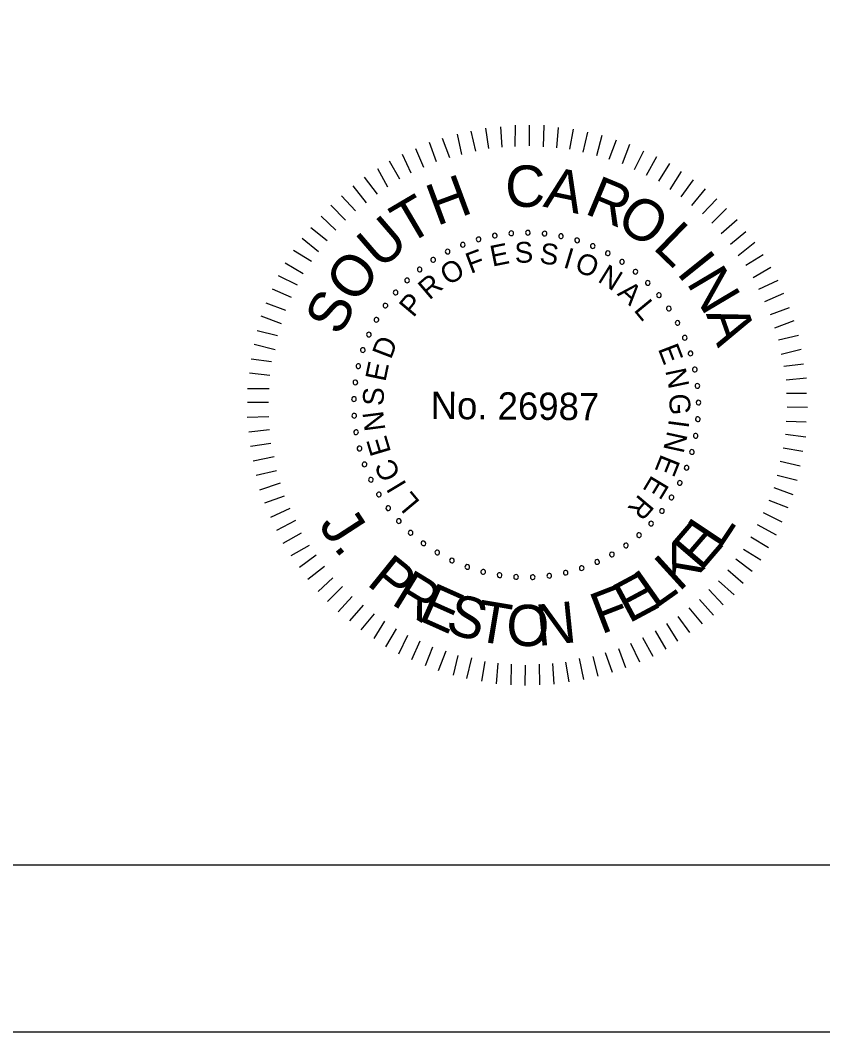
# Model space of a CAD drawing. Extents: x -125.5 to -89.4, y -5.1 to 16.9.
# Drawn here: x -102.74 to -100.338, y -5.066 to -2.039 of the extents above; entities that cross this region are included whole.
import ezdxf

# ---------------------------------------------------------------- set-up
doc = ezdxf.new("R2010")
doc.units = 0
for name, color, linetype in [('BR_BORDER LINES', 7, 'Continuous'), ('BR_TEXT', 7, 'Continuous'), ('Level 31', 7, 'Continuous')]:
    doc.layers.add(name, color=color, linetype=linetype)

msp = doc.modelspace()

# ---------------------------------------------------------------- linework, layer by layer
at = {"layer": 'BR_BORDER LINES'}
msp.add_line((-123.6994, -4.5662), (-90.0334, -4.5662), dxfattribs=at)
at = {"layer": 'BR_TEXT'}
for p, q in [((-101.2977, -2.419), (-101.3015, -2.3581)), ((-101.2582, -2.4168), (-101.2576, -2.3524)), ((-101.2161, -2.4146), (-101.2156, -2.3528)), ((-101.1741, -2.4175), (-101.1718, -2.3531)), ((-101.1338, -2.4204), (-101.129, -2.3595)), ((-101.418, -2.4404), (-101.4312, -2.3793)), ((-101.3767, -2.4304), (-101.3908, -2.3711)), ((-101.3372, -2.423), (-101.3461, -2.362)), ((-101.0952, -2.425), (-101.0844, -2.3642)), ((-101.0549, -2.4331), (-101.0407, -2.374)), ((-101.0138, -2.4437), (-100.9979, -2.3829)), ((-101.4937, -2.4629), (-101.5147, -2.4044)), ((-101.4541, -2.4504), (-101.476, -2.3927)), ((-100.977, -2.4543), (-100.9551, -2.397)), ((-100.9376, -2.4675), (-100.9157, -2.4093)), ((-101.5695, -2.4966), (-101.5957, -2.4406)), ((-101.5325, -2.4798), (-101.556, -2.4238)), ((-100.9017, -2.485), (-100.8738, -2.4294)), ((-100.8658, -2.5024), (-100.8345, -2.4469)), ((-101.604, -2.5144), (-101.6344, -2.46)), ((-100.8282, -2.5208), (-100.796, -2.467)), ((-101.6704, -2.5593), (-101.7095, -2.5083)), ((-101.6394, -2.5381), (-101.6698, -2.4838)), ((-100.795, -2.5451), (-100.761, -2.4913)), ((-101.7041, -2.5847), (-101.744, -2.5346)), ((-100.7617, -2.5668), (-100.7252, -2.5165)), ((-101.7369, -2.6094), (-101.7786, -2.5644)), ((-100.7293, -2.5928), (-100.6886, -2.5434)), ((-101.7663, -2.6366), (-101.8106, -2.5925)), ((-100.6977, -2.618), (-100.6545, -2.5737)), ((-100.6697, -2.6456), (-100.6264, -2.6022)), ((-101.7958, -2.6673), (-101.8392, -2.6248)), ((-101.8209, -2.6988), (-101.8704, -2.6598)), ((-100.6416, -2.6768), (-100.594, -2.6351)), ((-101.8469, -2.732), (-101.8964, -2.6922)), ((-100.6144, -2.7088), (-100.5677, -2.6705)), ((-100.5906, -2.7424), (-100.5414, -2.7033)), ((-101.8686, -2.761), (-101.9224, -2.728)), ((-100.5686, -2.7718), (-100.516, -2.7396)), ((-101.893, -2.7977), (-101.9467, -2.7656)), ((-100.5466, -2.8089), (-100.4931, -2.7776)), ((-101.9104, -2.8319), (-101.9668, -2.804)), ((-101.9279, -2.8687), (-101.9852, -2.8433)), ((-100.5288, -2.8433), (-100.4711, -2.8164)), ((-100.5111, -2.8804), (-100.4543, -2.856)), ((-101.9454, -2.9072), (-102.0035, -2.8852)), ((-100.4943, -2.9192), (-100.4374, -2.8982)), ((-101.9577, -2.9474), (-102.0193, -2.9246)), ((-100.4809, -2.9596), (-100.4232, -2.9378)), ((-101.97, -2.9833), (-102.0308, -2.9682)), ((-100.4708, -2.9957), (-100.4107, -2.9816)), ((-101.9772, -3.0253), (-102.0397, -3.0094)), ((-100.4626, -3.0378), (-100.4024, -3.0229)), ((-101.9878, -3.0613), (-102.0487, -3.0531)), ((-100.4543, -3.074), (-100.3951, -3.0667)), ((-101.9925, -3.1024), (-102.0542, -3.0951)), ((-100.4478, -3.1152), (-100.3868, -3.1088)), ((-101.9954, -3.1419), (-102.0597, -3.1414)), ((-100.4464, -3.1547), (-100.3863, -3.1552)), ((-101.9974, -3.183), (-102.06, -3.1825)), ((-100.4442, -3.1959), (-100.3833, -3.1964)), ((-101.9961, -3.226), (-102.0604, -3.2272)), ((-100.4471, -3.2388), (-100.3871, -3.241)), ((-101.9938, -3.2646), (-102.0556, -3.2718)), ((-100.4492, -3.2774), (-100.3883, -3.2856)), ((-101.9898, -3.3058), (-102.0509, -3.3148)), ((-100.4564, -3.3185), (-100.3972, -3.3284)), ((-101.9799, -3.3454), (-102.0426, -3.3586)), ((-100.4653, -3.3579), (-100.4053, -3.3721)), ((-101.9733, -3.3875), (-102.0344, -3.4016)), ((-100.4742, -3.3999), (-100.4143, -3.415)), ((-101.9616, -3.4245), (-102.0236, -3.4454)), ((-100.4848, -3.4367), (-100.4275, -3.4586)), ((-101.95, -3.4632), (-102.0085, -3.4842)), ((-100.4989, -3.4752), (-100.4424, -3.4971)), ((-101.9331, -3.5003), (-101.9908, -3.5272)), ((-101.9162, -3.5364), (-101.9731, -3.566)), ((-100.5163, -3.512), (-100.4599, -3.5399)), ((-100.5346, -3.5479), (-100.4774, -3.5784)), ((-101.8994, -3.5735), (-101.9537, -3.6048)), ((-100.553, -3.5846), (-100.5, -3.6168)), ((-101.8756, -3.6106), (-101.93, -3.6419)), ((-100.5756, -3.6213), (-100.5235, -3.6535)), ((-101.8544, -3.6399), (-101.9045, -3.6764)), ((-100.5981, -3.6503), (-100.5495, -3.6876)), ((-101.829, -3.6736), (-101.8791, -3.7127)), ((-100.6224, -3.6836), (-100.5764, -3.7234)), ((-101.8043, -3.7073), (-101.8485, -3.7481)), ((-100.6502, -3.7168), (-100.6033, -3.7584)), ((-101.7754, -3.7333), (-101.8204, -3.7784)), ((-100.6787, -3.7423), (-100.6362, -3.7882)), ((-101.7465, -3.7636), (-101.7889, -3.8095)), ((-100.7073, -3.7721), (-100.6648, -3.8188)), ((-101.714, -3.7895), (-101.7548, -3.8364)), ((-100.7392, -3.7976), (-100.6993, -3.8452)), ((-101.6808, -3.8156), (-101.7207, -3.8633)), ((-101.6501, -3.8373), (-101.6814, -3.8894)), ((-100.8057, -3.8443), (-100.7727, -3.8969)), ((-100.772, -3.8231), (-100.7364, -3.8714)), ((-101.6151, -3.8599), (-101.6464, -3.9137)), ((-100.8393, -3.8663), (-100.808, -3.9206)), ((-101.5809, -3.8799), (-101.608, -3.9355)), ((-101.5442, -3.8974), (-101.5687, -3.953)), ((-100.9135, -3.9026), (-100.8865, -3.9586)), ((-100.8773, -3.8857), (-100.8468, -3.9418)), ((-101.5057, -3.9149), (-101.5276, -3.9713)), ((-101.4663, -3.9272), (-101.4891, -3.9854)), ((-100.9892, -3.9311), (-100.9682, -3.9897)), ((-100.9496, -3.9194), (-100.9286, -3.9763)), ((-101.4304, -3.9395), (-101.4446, -3.9986)), ((-101.3892, -3.9467), (-101.4044, -4.0084)), ((-101.3499, -3.9582), (-101.3598, -4.0165)), ((-101.3104, -3.9628), (-101.3152, -4.0246)), ((-101.271, -3.9657), (-101.2715, -4.0275)), ((-101.1466, -3.9642), (-101.1428, -4.026)), ((-101.1079, -3.9602), (-101.098, -4.0186)), ((-101.0675, -3.9494), (-101.0542, -4.0113)), ((-101.0262, -3.9429), (-101.0112, -4.0022)), ((-101.229, -3.9686), (-101.2295, -4.0296)), ((-101.1869, -3.9664), (-101.1857, -4.0282))]:
    msp.add_line(p, q, dxfattribs=at)
for centre, start, end in [((-101.3681, -2.6945), 16.1422, 196.1422), ((-101.3681, -2.6945), 196.1422, 16.1422), ((-101.3196, -2.6831), 10.6038, 190.6038), ((-101.3196, -2.6831), 190.6038, 10.6038), ((-101.2702, -2.6764), 5.0653, 185.0653), ((-101.2702, -2.6764), 185.0653, 5.0653), ((-101.2204, -2.6745), 359.5268, 179.5268), ((-101.2204, -2.6745), 179.5268, 359.5268), ((-101.1707, -2.6774), 173.9884, 353.9884), ((-101.1707, -2.6774), 353.9884, 173.9884), ((-101.1214, -2.6851), 168.4499, 348.4499), ((-101.1214, -2.6851), 348.4499, 168.4499), ((-101.0732, -2.6976), 342.9114, 162.9114), ((-101.4607, -2.7311), 27.2191, 207.2191), ((-101.4153, -2.7106), 21.6807, 201.6807), ((-101.4153, -2.7106), 201.6807, 21.6807), ((-101.0732, -2.6976), 162.9114, 342.9114), ((-101.0263, -2.7146), 157.373, 337.373), ((-101.0263, -2.7146), 337.373, 157.373), ((-101.5039, -2.7559), 32.7576, 212.7576), ((-101.5039, -2.7559), 212.7576, 32.7576), ((-101.4607, -2.7311), 207.2191, 27.2191), ((-100.9814, -2.736), 151.8345, 331.8345), ((-100.9814, -2.736), 331.8345, 151.8345), ((-100.9387, -2.7617), 326.2961, 146.2961), ((-101.5445, -2.7848), 38.2961, 218.2961), ((-101.5445, -2.7848), 218.2961, 38.2961), ((-100.9387, -2.7617), 146.2961, 326.2961), ((-100.8987, -2.7914), 320.7576, 140.7576), ((-101.5821, -2.8175), 43.8345, 223.8345), ((-101.5821, -2.8175), 223.8345, 43.8345), ((-100.8987, -2.7914), 140.7576, 320.7576), ((-100.8617, -2.8249), 135.2191, 315.2191), ((-100.8617, -2.8249), 315.2191, 135.2191), ((-101.6164, -2.8536), 49.373, 229.373), ((-101.6164, -2.8536), 229.373, 49.373), ((-100.8282, -2.8617), 129.6807, 309.6807), ((-100.8282, -2.8617), 309.6807, 129.6807), ((-101.6471, -2.8929), 54.9114, 234.9114), ((-101.6471, -2.8929), 234.9114, 54.9114), ((-100.7983, -2.9016), 124.1422, 304.1422), ((-100.7983, -2.9016), 304.1422, 124.1422), ((-101.6738, -2.935), 60.4499, 240.4499), ((-101.6738, -2.935), 240.4499, 60.4499), ((-100.7724, -2.9442), 118.6038, 298.6038), ((-100.7724, -2.9442), 298.6038, 118.6038), ((-101.6964, -2.9794), 65.9884, 245.9884), ((-101.6964, -2.9794), 245.9884, 65.9884), ((-100.7508, -2.9891), 113.0653, 293.0653), ((-100.7508, -2.9891), 293.0653, 113.0653), ((-101.7145, -3.0258), 71.5268, 251.5268), ((-101.7145, -3.0258), 251.5268, 71.5268), ((-100.7336, -3.0359), 107.5268, 287.5268), ((-100.7336, -3.0359), 287.5268, 107.5268), ((-101.7281, -3.0738), 77.0653, 257.0653), ((-101.7281, -3.0738), 257.0653, 77.0653), ((-100.721, -3.0841), 101.9884, 281.9884), ((-100.721, -3.0841), 281.9884, 101.9884), ((-101.737, -3.1228), 82.6038, 262.6038), ((-101.737, -3.1228), 262.6038, 82.6038), ((-100.7131, -3.1333), 96.4499, 276.4499), ((-100.7131, -3.1333), 276.4499, 96.4499), ((-101.7411, -3.1724), 88.1422, 268.1422), ((-101.7411, -3.1724), 268.1422, 88.1422), ((-100.71, -3.183), 90.9114, 270.9114), ((-100.71, -3.183), 270.9114, 90.9114), ((-101.7404, -3.2223), 93.6807, 273.6807), ((-101.7404, -3.2223), 273.6807, 93.6807), ((-100.7118, -3.2328), 85.373, 265.373), ((-100.7118, -3.2328), 265.373, 85.373), ((-101.7349, -3.2718), 99.2191, 279.2191), ((-101.7349, -3.2718), 279.2191, 99.2191), ((-100.7183, -3.2822), 79.8345, 259.8345), ((-100.7183, -3.2822), 259.8345, 79.8345), ((-101.7246, -3.3206), 104.7576, 284.7576), ((-101.7246, -3.3206), 284.7576, 104.7576), ((-100.7295, -3.3308), 74.2961, 254.2961), ((-100.7295, -3.3308), 254.2961, 74.2961), ((-101.7097, -3.3681), 110.2961, 290.2961), ((-101.7097, -3.3681), 290.2961, 110.2961), ((-100.7454, -3.378), 68.7576, 248.7576), ((-100.7454, -3.378), 248.7576, 68.7576), ((-101.6903, -3.414), 115.8345, 295.8345), ((-101.6903, -3.414), 295.8345, 115.8345), ((-100.7658, -3.4235), 63.2191, 243.2191), ((-100.7658, -3.4235), 243.2191, 63.2191), ((-101.6665, -3.4578), 301.373, 121.373), ((-101.6665, -3.4578), 121.373, 301.373), ((-100.7904, -3.4668), 57.6807, 237.6807), ((-100.7904, -3.4668), 237.6807, 57.6807), ((-101.6386, -3.4991), 126.9114, 306.9114), ((-101.6386, -3.4991), 306.9114, 126.9114), ((-100.8192, -3.5075), 52.1422, 232.1422), ((-100.8192, -3.5075), 232.1422, 52.1422), ((-101.6069, -3.5375), 132.4499, 312.4499), ((-101.6069, -3.5375), 312.4499, 132.4499), ((-100.8517, -3.5452), 46.6038, 226.6038), ((-100.8517, -3.5452), 226.6038, 46.6038), ((-101.5716, -3.5727), 137.9884, 317.9884), ((-101.5716, -3.5727), 317.9884, 137.9884), ((-101.5331, -3.6043), 143.5268, 323.5268), ((-101.5331, -3.6043), 323.5268, 143.5268), ((-100.8877, -3.5797), 41.0653, 221.0653), ((-100.8877, -3.5797), 221.0653, 41.0653), ((-101.4917, -3.632), 149.0653, 329.0653), ((-101.4917, -3.632), 329.0653, 149.0653), ((-100.9688, -3.6374), 29.9884, 209.9884), ((-100.9269, -3.6105), 35.5268, 215.5268), ((-100.9269, -3.6105), 215.5268, 35.5268), ((-101.4478, -3.6556), 154.6038, 334.6038), ((-101.4478, -3.6556), 334.6038, 154.6038), ((-101.0132, -3.6601), 24.4499, 204.4499), ((-101.0132, -3.6601), 204.4499, 24.4499), ((-100.9688, -3.6374), 209.9884, 29.9884), ((-101.4018, -3.6749), 160.1422, 340.1422), ((-101.4018, -3.6749), 340.1422, 160.1422), ((-101.3542, -3.6896), 165.6807, 345.6807), ((-101.3542, -3.6896), 345.6807, 165.6807), ((-101.3054, -3.6997), 351.2191, 171.2191), ((-101.1074, -3.6921), 13.373, 193.373), ((-101.1074, -3.6921), 193.373, 13.373), ((-101.0595, -3.6784), 18.9114, 198.9114), ((-101.0595, -3.6784), 198.9114, 18.9114), ((-101.3054, -3.6997), 171.2191, 351.2191), ((-101.2559, -3.705), 356.7576, 176.7576), ((-101.2559, -3.705), 176.7576, 356.7576), ((-101.2061, -3.7055), 2.2961, 182.2961), ((-101.2061, -3.7055), 182.2961, 2.2961), ((-101.1564, -3.7012), 7.8345, 187.8345), ((-101.1564, -3.7012), 187.8345, 7.8345)]:
    msp.add_arc(centre, 0.00701, start, end, dxfattribs=at)
at = {"layer": 'Level 31'}
msp.add_lwpolyline([(-125.5328, 16.9339), (-125.5328, -5.0661), (-89.5328, -5.0661), (-89.5328, 16.9339)], dxfattribs=at)

# ---------------------------------------------------------------- texts
at = {"layer": 'BR_TEXT'}
for s, height, rotation, p in [('C', 0.1241, 359.5482, (-101.2889, -2.5969)), ('H', 0.1241, 20.3637, (-101.4933, -2.6552)), ('A', 0.1241, 348.1981, (-101.1775, -2.5961)), ('R', 0.1241, 337.4344, (-101.0542, -2.616)), ('T', 0.1241, 30.4992, (-101.5812, -2.7128)), ('O', 0.1239, 326.5869, (-100.962, -2.6528)), ('U', 0.1241, 40.8022, (-101.6624, -2.7875)), ('L', 0.1241, 315.9488, (-100.8494, -2.7205)), ('F', 0.0622, 20.6127, (-101.392, -2.7981)), ('E', 0.0622, 11.4103, (-101.3269, -2.7764)), ('S', 0.0622, 2.208, (-101.2591, -2.7654)), ('S', 0.0622, 352.6608, (-101.1878, -2.7657)), ('I', 0.0622, 343.1136, (-101.1175, -2.7777)), ('O', 0.1241, 52.0267, (-101.7369, -2.8914)), ('O', 0.0622, 338.4392, (-101.0841, -2.7878)), ('I', 0.1241, 308.6613, (-100.778, -2.7948)), ('O', 0.0622, 30.8477, (-101.4594, -2.8341)), ('N', 0.0622, 328.2042, (-101.0145, -2.8192)), ('N', 0.1241, 300.7037, (-100.7474, -2.8242)), ('R', 0.0622, 40.3949, (-101.5156, -2.878)), ('A', 0.0622, 318.657, (-100.9555, -2.8592)), ('S', 0.1239, 63.2511, (-101.7823, -2.9871)), ('P', 0.0622, 49.9421, (-101.5636, -2.9306)), ('L', 0.0622, 309.4546, (-100.9057, -2.9066)), ('A', 0.1241, 289.4792, (-100.6882, -2.9172)), ('D', 0.0622, 69.0364, (-101.6306, -3.0559)), ('E', 0.0622, 291.049, (-100.8319, -3.0219)), ('E', 0.0622, 78.2388, (-101.6472, -3.1226)), ('N', 0.0622, 281.8466, (-100.8097, -3.0869)), ('S', 0.0622, 87.786, (-101.6529, -3.1936)), ('No. 26987', 0.08175, 359.5268, (-101.5118, -3.232)), ('G', 0.0622, 272.2995, (-100.7979, -3.1572)), ('N', 0.0622, 97.3332, (-101.6467, -3.2646)), ('I', 0.0622, 262.4084, (-100.7983, -3.231)), ('E', 0.0622, 106.5355, (-101.6297, -3.3312)), ('N', 0.0622, 257.7339, (-100.8028, -3.2656)), ('C', 0.0622, 116.4266, (-101.5998, -3.3987)), ('E', 0.0622, 248.1867, (-100.8209, -3.3346)), ('I', 0.0622, 121.1011, (-101.5818, -3.4285)), ('E', 0.0622, 238.9844, (-100.8488, -3.3973)), ('L', 0.0622, 129.9595, (-101.5411, -3.4807)), ('R', 0.0622, 229.782, (-100.8865, -3.4548)), ('J', 0.1236, 302.9559, (-101.849, -3.5492)), ('E', 0.1236, 49.3639, (-100.703, -3.6911)), ('L', 0.1236, 56.4247, (-100.6455, -3.6233)), ('K', 0.1236, 42.3031, (-100.7683, -3.7512)), ('.', 0.1236, 309.3974, (-101.8049, -3.6172)), ('P', 0.1236, 321.1035, (-101.7065, -3.7264)), ('R', 0.1236, 328.5359, (-101.6332, -3.7844)), ('E', 0.1236, 28.1814, (-100.9186, -3.8452)), ('L', 0.1236, 35.2422, (-100.8406, -3.8028)), ('E', 0.1236, 335.9684, (-101.5531, -3.8325)), ('F', 0.1236, 21.1206, (-101.0013, -3.8776)), ('S', 0.1236, 343.0292, (-101.4718, -3.8682)), ('T', 0.1236, 350.4617, (-101.3821, -3.8947)), ('N', 0.1236, 5.8221, (-101.1902, -3.9118)), ('O', 0.1236, 358.1419, (-101.2867, -3.9097))]:
    msp.add_text(s, height=height, rotation=rotation, dxfattribs=at).set_placement(p)

doc.saveas('drawing.dxf')
